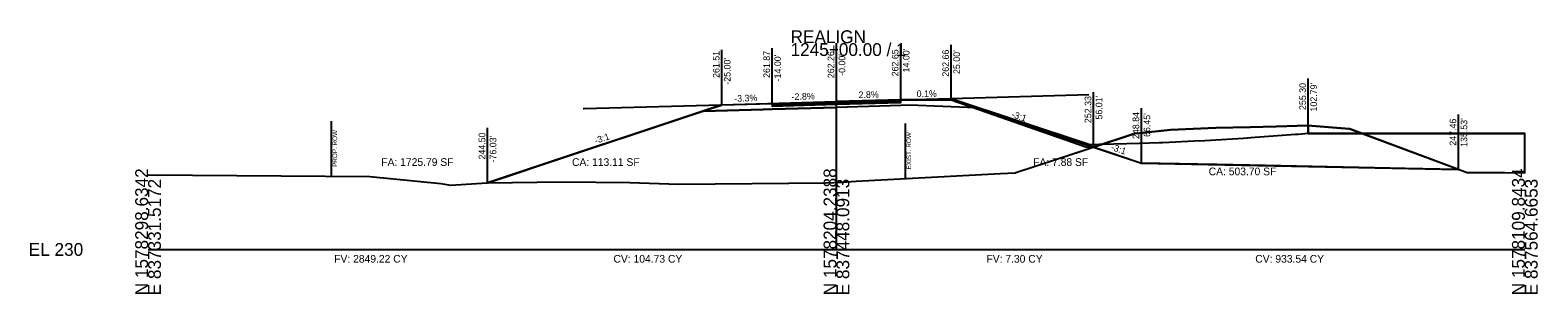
# Model space of a CAD drawing. Extents: x -26 to 6303, y -16 to 9563.
# Drawn here: x 1974.3 to 2302.8, y 5990.3 to 6047.8 of the extents above; entities that cross this region are included whole.
import ezdxf

# ---------------------------------------------------------------- set-up
doc = ezdxf.new("R2010")
doc.units = 0
for name, color, linetype in [('ASPHALT_19MM1', 7, 'Continuous'), ('ASPHALT_9_5MM1', 7, 'Continuous'), ('CONST_DCH', 7, 'Continuous'), ('CONST_LV3', 7, 'Continuous'), ('Draft_XS_Grid', 7, 'Continuous'), ('DTM_P_FINISHED_GRADE', 7, 'Continuous'), ('DTM_P_FINISHED_GRADE2', 7, 'Continuous'), ('DTM_TEMP_DROP', 7, 'Continuous'), ('DTM_X_GROUND', 7, 'Continuous'), ('TRANS_EOP_PAVED', 7, 'Continuous'), ('TRANS_PAVED_SHOULDERS', 7, 'Continuous'), ('XS_CELL', 7, 'Continuous'), ('XS_M_SHAPES_EARTHWORK', 7, 'Continuous'), ('XS_P_ASPHALT', 7, 'Continuous'), ('XS_P_GROUND', 7, 'Continuous'), ('XS_P_ROW', 7, 'Continuous'), ('XS_P_SHOULDER', 7, 'Continuous'), ('XS_P_SUBGRADE_GRANULAR', 7, 'Continuous'), ('XS_P_TX_CLEARZONE', 7, 'Continuous'), ('XS_P_TX_FS_BS', 7, 'Continuous'), ('XS_SHEET_EW_TX_AREA', 7, 'Continuous'), ('XS_SHEET_EW_TX_VOLUME', 7, 'Continuous'), ('XS_X_ROW', 7, 'Continuous')]:
    doc.layers.add(name, color=color, linetype=linetype)

msp = doc.modelspace()

# ---------------------------------------------------------------- linework, layer by layer
at = {"layer": 'ASPHALT_19MM1'}
msp.add_lwpolyline([(2136, 6031.53), (2136, 6031.26), (2150, 6031.66), (2150, 6031.66), (2164, 6032.05), (2164, 6032.05), (2164, 6032.32), (2164, 6032.32), (2164, 6032.32), (2150, 6031.93), (2150, 6031.93), (2136, 6031.53), (2136, 6031.53)], dxfattribs=at)
at = {"layer": 'ASPHALT_9_5MM1'}
msp.add_lwpolyline([(2136, 6031.87), (2150, 6032.26), (2150, 6032.26), (2164, 6032.65), (2164, 6032.65), (2164, 6032.53), (2164, 6032.53), (2150, 6032.13), (2150, 6032.13), (2136, 6031.74), (2136, 6031.87)], dxfattribs=at)
at = {"layer": 'CONST_LV3'}
for points in [[(2094.83, 6030.75), (2094.85, 6030.75), (2095, 6030.72), (2095, 6030.72), (2095, 6030.72), (2095, 6030.72), (2095, 6030.72), (2095, 6030.72), (2095, 6030.72), (2124.89, 6031.56), (2125, 6031.56), (2149.91, 6032.26), (2150, 6032.26), (2150, 6032.26), (2175, 6032.96), (2175, 6032.96), (2205, 6033.8)], [(2094.83, 6021.59), (2094.85, 6021.59), (2095, 6021.56), (2095, 6021.56), (2095, 6021.56), (2095, 6021.56), (2095, 6021.56), (2095, 6021.56), (2095, 6021.56), (2124.89, 6031.52), (2125, 6031.56), (2149.91, 6032.26), (2150, 6032.26), (2150, 6032.26), (2175, 6032.96), (2175, 6032.96), (2205, 6022.96)], [(2164, 6032.65), (2164, 6032.65), (2150, 6032.26)], [(2175, 6032.66), (2175, 6032.66), (2164, 6032.65)]]:
    msp.add_lwpolyline(points, dxfattribs=at)
at = {"layer": 'DTM_P_FINISHED_GRADE'}
msp.add_lwpolyline([(2252.79, 6025.3), (2260.4, 6025.3), (2261.49, 6025.3), (2270.34, 6025.3), (2273.19, 6025.3), (2280.22, 6025.3), (2281.63, 6025.3), (2281.77, 6025.3), (2284.43, 6025.3), (2287.26, 6025.3), (2287.95, 6025.3), (2289.43, 6025.3), (2291, 6025.3), (2291.52, 6025.3), (2297.35, 6025.3), (2298.67, 6025.3), (2298.77, 6025.3), (2299.64, 6025.3), (2300, 6025.3)], dxfattribs=at)
at = {"layer": 'DTM_P_FINISHED_GRADE2'}
msp.add_lwpolyline([(2073.97, 6014.5), (2073.97, 6014.5), (2074.04, 6014.52), (2082.08, 6017.22), (2083.77, 6017.79), (2122.21, 6030.59), (2124.98, 6031.5), (2125, 6031.51), (2136, 6031.87), (2150, 6032.26), (2164, 6032.65), (2175, 6032.66), (2204.38, 6022.36), (2206.01, 6022.33)], dxfattribs=at)
at = {"layer": 'DTM_X_GROUND'}
msp.add_lwpolyline([(2000, 6016.26), (2048.33, 6015.94), (2063.81, 6014.38), (2065.97, 6014.04), (2073.85, 6014.5), (2090.23, 6014.77), (2104.99, 6014.57), (2115.55, 6014.24), (2147.65, 6014.54), (2151.29, 6014.71), (2154.32, 6014.87), (2185.78, 6016.57), (2188.93, 6016.73), (2189.11, 6016.75), (2213.71, 6024.87), (2214.94, 6025.28), (2216.05, 6025.39), (2222.79, 6026.07), (2232.67, 6026.53), (2240.12, 6026.68), (2245.83, 6026.85), (2252.69, 6027.05), (2261.7, 6026.34), (2261.83, 6026.33), (2262.23, 6026.18), (2287.44, 6016.75), (2295.61, 6016.75), (2300, 6016.72)], dxfattribs=at)
at = {"layer": 'TRANS_PAVED_SHOULDERS'}
msp.add_lwpolyline([(2136, 6031.74), (2136, 6031.53), (2150, 6031.93), (2150, 6031.93), (2164, 6032.32), (2164, 6032.32), (2164, 6032.53), (2164, 6032.53), (2164, 6032.53), (2150, 6032.13), (2150, 6032.13), (2136, 6031.74), (2136, 6031.74)], dxfattribs=at)
at = {"layer": 'XS_CELL'}
for p, q in [((2150, 6000), (2150, 6045)), ((2000, 6000), (2150, 6000)), ((2150, 6000), (2300, 6000))]:
    msp.add_line(p, q, dxfattribs=at)
at = {"layer": 'XS_M_SHAPES_EARTHWORK'}
for points in [[(2073.97, 6014.5), (2090.23, 6014.77), (2104.99, 6014.57), (2115.55, 6014.24), (2147.65, 6014.54), (2151.29, 6014.71), (2154.32, 6014.87), (2185.78, 6016.57), (2188.93, 6016.73), (2189.11, 6016.75), (2207.76, 6022.9), (2204.45, 6022.85), (2180.4, 6030.86), (2166, 6031.44), (2164, 6031.38), (2150, 6030.99), (2136, 6030.6), (2134, 6030.54), (2121.01, 6030.18)], [(2207.76, 6022.9), (2213.71, 6024.87), (2214.94, 6025.28), (2216.05, 6025.39), (2222.79, 6026.07), (2232.67, 6026.53), (2240.12, 6026.68), (2245.83, 6026.85), (2252.69, 6027.05), (2252.79, 6027.04), (2252.79, 6025.3), (2250.67, 6025.1), (2250.37, 6025.08), (2250.37, 6025.08), (2250.01, 6025.05), (2240.29, 6024.31), (2238.7, 6024.22), (2230.3, 6023.71), (2227.93, 6023.6), (2221.1, 6023.29), (2220.87, 6023.28), (2220.36, 6023.26), (2216.02, 6023.12), (2210.46, 6022.95)], [(2252.79, 6025.3), (2252.79, 6027.04), (2261.7, 6026.34), (2261.83, 6026.33), (2262.23, 6026.18), (2264.57, 6025.3), (2261.49, 6025.3), (2260.4, 6025.3)], [(2264.57, 6025.3), (2287.44, 6016.75), (2295.61, 6016.75), (2300, 6016.72), (2300, 6025.3), (2299.64, 6025.3), (2298.77, 6025.3), (2298.67, 6025.3), (2297.35, 6025.3), (2291.52, 6025.3), (2291, 6025.3), (2289.43, 6025.3), (2287.95, 6025.3), (2287.26, 6025.3), (2284.43, 6025.3), (2281.77, 6025.3), (2281.63, 6025.3), (2280.22, 6025.3), (2273.19, 6025.3), (2270.34, 6025.3)]]:
    msp.add_lwpolyline(points, close=True, dxfattribs=at)
at = {"layer": 'XS_P_GROUND'}
for points in [[(2175, 6032.66), (2206.01, 6022.33)], [(2175, 6032.66), (2178.19, 6031.6), (2178.19, 6031.6), (2186.48, 6028.83), (2186.48, 6028.83), (2186.48, 6028.83), (2192.2, 6026.93), (2192.2, 6026.93), (2193.79, 6026.4), (2193.79, 6026.4), (2193.79, 6026.4), (2193.79, 6026.4), (2193.79, 6026.4), (2193.8, 6026.39), (2193.81, 6026.39), (2193.81, 6026.39), (2193.81, 6026.39), (2193.81, 6026.39), (2193.82, 6026.39), (2193.83, 6026.38), (2193.84, 6026.38), (2193.84, 6026.38), (2193.85, 6026.38), (2193.86, 6026.37), (2193.86, 6026.37), (2193.86, 6026.37), (2193.86, 6026.37), (2193.87, 6026.37), (2193.88, 6026.37), (2193.89, 6026.36), (2193.89, 6026.36), (2193.89, 6026.36), (2193.9, 6026.36), (2193.91, 6026.36), (2193.92, 6026.35), (2193.92, 6026.35), (2193.93, 6026.35), (2193.94, 6026.35), (2193.95, 6026.34), (2193.95, 6026.34), (2193.96, 6026.34), (2193.96, 6026.34), (2193.97, 6026.34), (2193.99, 6026.33), (2193.99, 6026.33), (2193.99, 6026.33), (2193.99, 6026.33), (2193.99, 6026.33), (2193.99, 6026.33), (2194, 6026.33), (2194.01, 6026.32), (2194.02, 6026.32), (2194.02, 6026.32), (2194.03, 6026.32), (2194.03, 6026.32), (2194.03, 6026.32), (2194.04, 6026.31), (2194.06, 6026.31), (2194.06, 6026.31), (2194.07, 6026.3), (2194.07, 6026.3), (2194.08, 6026.3), (2194.1, 6026.29), (2194.1, 6026.29), (2194.1, 6026.29), (2194.11, 6026.29), (2194.92, 6026.02), (2194.92, 6026.02), (2210.74, 6020.75), (2211.75, 6020.41), (2211.75, 6020.41), (2216.45, 6018.84), (2216.45, 6018.84)], [(2125, 6031.51), (2073.97, 6014.5)], [(2252.79, 6025.3), (2250.67, 6025.1), (2250.37, 6025.08), (2250.37, 6025.08), (2250.01, 6025.05), (2240.29, 6024.31), (2238.7, 6024.22), (2230.3, 6023.71), (2227.93, 6023.6), (2221.1, 6023.29), (2220.87, 6023.28), (2220.36, 6023.26), (2216.02, 6023.12), (2210.46, 6022.95), (2204.06, 6022.84)], [(2240.07, 6018.37), (2240.07, 6018.37), (2232.9, 6018.52), (2232.9, 6018.52), (2216.45, 6018.84)], [(2285.53, 6017.46), (2285.25, 6017.47), (2273.98, 6017.69), (2240.07, 6018.37)]]:
    msp.add_lwpolyline(points, dxfattribs=at)
at = {"layer": 'XS_P_ROW'}
msp.add_line((2040, 6016), (2040, 6028), dxfattribs=at)
at = {"layer": 'XS_P_SHOULDER'}
for points in [[(2125, 6031.51), (2136, 6031.87), (2136, 6031.87)], [(2175, 6032.66), (2175, 6032.66), (2164, 6032.65)]]:
    msp.add_lwpolyline(points, dxfattribs=at)
at = {"layer": 'XS_P_SUBGRADE_GRANULAR'}
for points in [[(2121.01, 6030.18), (2121.01, 6030.18), (2134, 6030.54), (2136, 6030.6), (2136, 6030.6)], [(2136, 6030.6), (2150, 6030.99), (2150, 6030.99)], [(2164, 6031.38), (2164, 6031.38), (2150, 6030.99)], [(2180.4, 6030.86), (2180.4, 6030.86), (2166, 6031.44), (2166, 6031.44), (2164, 6031.38)]]:
    msp.add_lwpolyline(points, dxfattribs=at)
at = {"layer": 'XS_P_TX_CLEARZONE'}
for p, q in [((2125, 6031.51), (2125, 6043.51)), ((2136, 6031.87), (2136, 6043.87)), ((2150, 6032.26), (2150, 6044.26)), ((2164, 6032.65), (2164, 6044.65)), ((2175, 6032.66), (2175, 6044.66)), ((2175, 6032.66), (2175, 6044.66)), ((2252.79, 6025.3), (2252.79, 6037.3)), ((2206.01, 6022.33), (2206.01, 6034.33)), ((2216.45, 6018.84), (2216.45, 6030.84)), ((2285.53, 6017.46), (2285.53, 6029.46)), ((2073.97, 6014.5), (2073.97, 6026.5))]:
    msp.add_line(p, q, dxfattribs=at)
at = {"layer": 'XS_P_TX_FS_BS'}
for p, q in [((2206.01, 6022.32), (2216.45, 6018.84)), ((2216.45, 6018.84), (2285.53, 6017.46))]:
    msp.add_line(p, q, dxfattribs=at)
for points in [[(2262.23, 6026.18), (2261.83, 6026.33), (2261.7, 6026.34), (2252.69, 6027.05), (2245.83, 6026.85), (2240.12, 6026.68), (2232.67, 6026.53), (2222.79, 6026.07), (2216.05, 6025.39), (2214.94, 6025.28), (2213.71, 6024.87), (2206.01, 6022.32)], [(2285.53, 6017.46), (2264.57, 6025.3), (2262.23, 6026.18)]]:
    msp.add_lwpolyline(points, dxfattribs=at)
at = {"layer": 'XS_X_ROW'}
msp.add_line((2165.07, 6015.45), (2165.07, 6027.45), dxfattribs=at)

# ---------------------------------------------------------------- texts
at = {"layer": 'CONST_DCH'}
for p in [(2135.92, 6031.75), (2149.92, 6032.14), (2163.92, 6032.53), (2216.37, 6018.72)]:
    msp.add_text('X', height=0.24, dxfattribs=at).set_placement(p)
at = {"layer": 'Draft_XS_Grid'}
msp.add_text('-', height=0.0001, dxfattribs=at).set_placement((2000, 6000))
at = {"layer": 'DTM_TEMP_DROP'}
for p in [(2252.71, 6025.18), (2205.93, 6022.21), (2073.89, 6014.38)]:
    msp.add_text('X', height=0.24, dxfattribs=at).set_placement(p)
at = {"layer": 'DTM_X_GROUND'}
msp.add_text('X', height=0.24, dxfattribs=at).set_placement((2203.99, 6022.72))
at = {"layer": 'TRANS_EOP_PAVED'}
for p in [(2174.92, 6032.54), (2205.93, 6022.21), (2073.89, 6014.38)]:
    msp.add_text('X', height=0.24, dxfattribs=at).set_placement(p)
at = {"layer": 'XS_CELL'}
for s, p in [('1245+00.00 / 1', (2140, 6042.2)), ('REALIGN', (2140, 6045)), ('EL 230', (1974, 5998.6))]:
    msp.add_text(s, height=2.8, dxfattribs=at).set_placement(p)
for s, p in [('N 1578298.6342', (2000, 5990)), ('N 1578204.2388', (2150, 5990)), ('N 1578109.8434', (2300, 5990)), ('E 837331.5172', (2002.8, 5990)), ('E 837448.0913', (2152.8, 5990)), ('E 837564.6653', (2302.8, 5990))]:
    msp.add_text(s, height=2.8, rotation=90, dxfattribs=at).set_placement(p)
at = {"layer": 'XS_P_ASPHALT'}
msp.add_text('X', height=0.24, dxfattribs=at).set_placement((2285.45, 6017.34))
at = {"layer": 'XS_P_ROW'}
msp.add_text('PROP. ROW', height=1, rotation=90, dxfattribs=at).set_placement((2041.2, 6018))
at = {"layer": 'XS_P_SUBGRADE_GRANULAR'}
for p in [(2174.92, 6032.54), (2124.92, 6031.39)]:
    msp.add_text('X', height=0.24, dxfattribs=at).set_placement(p)
at = {"layer": 'XS_P_TX_CLEARZONE'}
for s, p in [('261.51', (2124.52, 6037.41)), ('261.87', (2135.52, 6037.41)), ("-14.00'", (2137.92, 6036.66)), ('262.26', (2149.52, 6037.36)), ("-0.00'", (2151.92, 6037.87)), ('262.65', (2163.52, 6037.76)), ("14.00'", (2165.92, 6038.62)), ('262.66', (2174.52, 6037.69)), ("25.00'", (2176.92, 6038.27)), ("-25.00'", (2126.92, 6035.94)), ('255.30', (2252.31, 6030.42)), ("102.79'", (2254.71, 6030.09)), ('252.33', (2205.53, 6027.57)), ("56.01'", (2207.93, 6028.34)), ('248.84', (2215.97, 6024.09)), ("66.45'", (2218.37, 6024.54)), ('244.50', (2073.49, 6019.62)), ('247.46', (2285.05, 6022.63)), ("135.53'", (2287.45, 6022.37)), ("-76.03'", (2075.89, 6018.97))]:
    msp.add_text(s, height=1.44, rotation=90, dxfattribs=at).set_placement(p)
at = {"layer": 'XS_P_TX_FS_BS'}
for s, rotation, p in [('-3.3%', 1.8786, (2127.75, 6032.2)), ('-2.8%', 1.6039, (2140.25, 6032.59)), ('2.8%', 1.6039, (2154.84, 6033)), ('0.1%', 0.0458, (2167.48, 6033.25)), ('-3:1', 341.3279, (2188.01, 6028.9)), ('-3:1', 18.4332, (2097.57, 6023)), ('-3:1', 341.5599, (2209.7, 6021.73))]:
    msp.add_text(s, height=1.44, rotation=rotation, dxfattribs=at).set_placement(p)
at = {"layer": 'XS_SHEET_EW_TX_AREA'}
for s, p in [('FA: 1725.79 SF', (2050.82, 6018.22)), ('CA: 113.11 SF', (2092.38, 6018.22)), ('FA: 7.88 SF', (2192.87, 6018.22)), ('CA: 503.70 SF', (2231.12, 6016.18))]:
    msp.add_text(s, height=1.68, dxfattribs=at).set_placement(p)
at = {"layer": 'XS_SHEET_EW_TX_VOLUME'}
for s, p in [('FV: 2849.22 CY', (2040.56, 5997.12)), ('CV: 104.73 CY', (2101.42, 5997.12)), ('FV: 7.30 CY', (2182.69, 5997.12)), ('CV: 933.54 CY', (2241.27, 5997.12))]:
    msp.add_text(s, height=1.68, dxfattribs=at).set_placement(p)
at = {"layer": 'XS_X_ROW'}
msp.add_text('EXIST. ROW', height=1, rotation=90, dxfattribs=at).set_placement((2166.27, 6017.45))

doc.saveas('drawing.dxf')
